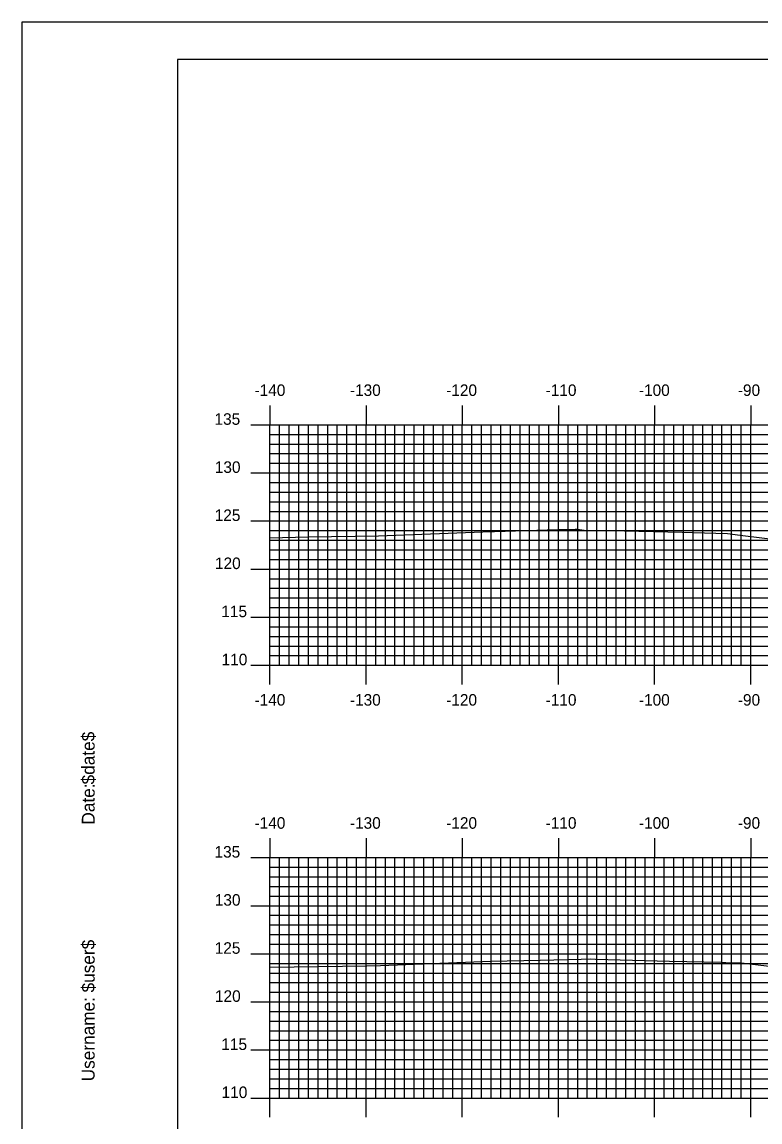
# Model space of a CAD drawing. Extents: x 842962 to 843305, y 363538 to 363758.
# Drawn here: x 842962.1 to 843038.9, y 363643.2 to 363757.6 of the extents above; entities that cross this region are included whole.
import ezdxf

# ---------------------------------------------------------------- set-up
doc = ezdxf.new("R2010")
doc.units = 0
for name, color, linetype in [('BORDER', 7, 'Continuous'), ('H_V ANNOTATION', 7, 'Continuous'), ('M_Roadway_Centerline', 7, 'Continuous'), ('MAJOR', 7, 'Continuous'), ('MINOR', 7, 'Continuous'), ('PLOT BOUNDARY', 7, 'Continuous'), ('S_Roadway_Centerline', 7, 'Continuous')]:
    doc.layers.add(name, color=color, linetype=linetype)

msp = doc.modelspace()

# ---------------------------------------------------------------- linework, layer by layer
at = {"layer": 'BORDER'}
msp.add_lwpolyline([(842978.31, 363543.72), (843298.31, 363543.72), (843298.31, 363753.72), (842978.31, 363753.72)], close=True, dxfattribs=at)
at = {"layer": 'MAJOR'}
for p, q in [((842987.91, 363717.73), (842987.91, 363715.72)), ((842997.91, 363717.73), (842997.91, 363715.72)), ((843007.91, 363717.73), (843007.91, 363715.72)), ((843017.91, 363717.73), (843017.91, 363715.72)), ((843027.91, 363717.73), (843027.91, 363715.72)), ((843037.91, 363717.73), (843037.91, 363715.72)), ((842985.91, 363715.72), (842987.91, 363715.72)), ((842987.91, 363715.72), (843267.91, 363715.72)), ((842987.91, 363690.72), (842987.91, 363715.72)), ((842987.91, 363690.72), (842987.91, 363715.72)), ((842987.91, 363715.72), (843267.91, 363715.72)), ((842997.91, 363690.72), (842997.91, 363715.72)), ((843007.91, 363690.72), (843007.91, 363715.72)), ((843017.91, 363690.72), (843017.91, 363715.72)), ((843027.91, 363690.72), (843027.91, 363715.72)), ((843037.91, 363690.72), (843037.91, 363715.72)), ((842985.91, 363710.72), (842987.91, 363710.72)), ((842987.91, 363710.72), (843267.91, 363710.72)), ((842985.91, 363705.72), (842987.91, 363705.72)), ((842987.91, 363705.72), (843267.91, 363705.72)), ((842985.91, 363700.72), (842987.91, 363700.72)), ((842987.91, 363700.72), (843267.91, 363700.72)), ((842985.91, 363695.72), (842987.91, 363695.72)), ((842987.91, 363695.72), (843267.91, 363695.72)), ((842985.91, 363690.72), (842987.91, 363690.72)), ((842987.91, 363690.72), (843267.91, 363690.72)), ((842987.91, 363690.72), (843267.91, 363690.72)), ((842987.91, 363688.72), (842987.91, 363690.72)), ((842997.91, 363688.72), (842997.91, 363690.72)), ((843007.91, 363688.72), (843007.91, 363690.72)), ((843017.91, 363688.72), (843017.91, 363690.72)), ((843027.91, 363688.72), (843027.91, 363690.72)), ((843037.91, 363688.72), (843037.91, 363690.72)), ((842987.91, 363672.73), (842987.91, 363670.72)), ((842997.91, 363672.73), (842997.91, 363670.72)), ((843007.91, 363672.73), (843007.91, 363670.72)), ((843017.91, 363672.73), (843017.91, 363670.72)), ((843027.91, 363672.73), (843027.91, 363670.72)), ((843037.91, 363672.73), (843037.91, 363670.72)), ((842985.91, 363670.72), (842987.91, 363670.72)), ((842987.91, 363670.72), (843267.91, 363670.72)), ((842987.91, 363645.72), (842987.91, 363670.72)), ((842987.91, 363645.72), (842987.91, 363670.72)), ((842987.91, 363670.72), (843267.91, 363670.72)), ((842997.91, 363645.72), (842997.91, 363670.72)), ((843007.91, 363645.72), (843007.91, 363670.72)), ((843017.91, 363645.72), (843017.91, 363670.72)), ((843027.91, 363645.72), (843027.91, 363670.72)), ((843037.91, 363645.72), (843037.91, 363670.72)), ((842985.91, 363665.72), (842987.91, 363665.72)), ((842987.91, 363665.72), (843267.91, 363665.72)), ((842985.91, 363660.72), (842987.91, 363660.72)), ((842987.91, 363660.72), (843267.91, 363660.72)), ((842985.91, 363655.72), (842987.91, 363655.72)), ((842987.91, 363655.72), (843267.91, 363655.72)), ((842985.91, 363650.72), (842987.91, 363650.72)), ((842987.91, 363650.72), (843267.91, 363650.72)), ((842985.91, 363645.72), (842987.91, 363645.72)), ((842987.91, 363645.72), (843267.91, 363645.72)), ((842987.91, 363645.72), (843267.91, 363645.72)), ((842987.91, 363643.72), (842987.91, 363645.72)), ((842997.91, 363643.72), (842997.91, 363645.72)), ((843007.91, 363643.72), (843007.91, 363645.72)), ((843017.91, 363643.72), (843017.91, 363645.72)), ((843027.91, 363643.72), (843027.91, 363645.72)), ((843037.91, 363643.72), (843037.91, 363645.72))]:
    msp.add_line(p, q, dxfattribs=at)
at = {"layer": 'MINOR'}
for p, q in [((842988.91, 363690.72), (842988.91, 363715.72)), ((842989.91, 363690.72), (842989.91, 363715.72)), ((842990.91, 363690.72), (842990.91, 363715.72)), ((842991.91, 363690.72), (842991.91, 363715.72)), ((842992.91, 363690.72), (842992.91, 363715.72)), ((842993.91, 363690.72), (842993.91, 363715.72)), ((842994.91, 363690.72), (842994.91, 363715.72)), ((842995.91, 363690.72), (842995.91, 363715.72)), ((842996.91, 363690.72), (842996.91, 363715.72)), ((842998.91, 363690.72), (842998.91, 363715.72)), ((842999.91, 363690.72), (842999.91, 363715.72)), ((843000.91, 363690.72), (843000.91, 363715.72)), ((843001.91, 363690.72), (843001.91, 363715.72)), ((843002.91, 363690.72), (843002.91, 363715.72)), ((843003.91, 363690.72), (843003.91, 363715.72)), ((843004.91, 363690.72), (843004.91, 363715.72)), ((843005.91, 363690.72), (843005.91, 363715.72)), ((843006.91, 363690.72), (843006.91, 363715.72)), ((843008.91, 363690.72), (843008.91, 363715.72)), ((843009.91, 363690.72), (843009.91, 363715.72)), ((843010.91, 363690.72), (843010.91, 363715.72)), ((843011.91, 363690.72), (843011.91, 363715.72)), ((843012.91, 363690.72), (843012.91, 363715.72)), ((843013.91, 363690.72), (843013.91, 363715.72)), ((843014.91, 363690.72), (843014.91, 363715.72)), ((843015.91, 363690.72), (843015.91, 363715.72)), ((843016.91, 363690.72), (843016.91, 363715.72)), ((843018.91, 363690.72), (843018.91, 363715.72)), ((843019.91, 363690.72), (843019.91, 363715.72)), ((843020.91, 363690.72), (843020.91, 363715.72)), ((843021.91, 363690.72), (843021.91, 363715.72)), ((843022.91, 363690.72), (843022.91, 363715.72)), ((843023.91, 363690.72), (843023.91, 363715.72)), ((843024.91, 363690.72), (843024.91, 363715.72)), ((843025.91, 363690.72), (843025.91, 363715.72)), ((843026.91, 363690.72), (843026.91, 363715.72)), ((843028.91, 363690.72), (843028.91, 363715.72)), ((843029.91, 363690.72), (843029.91, 363715.72)), ((843030.91, 363690.72), (843030.91, 363715.72)), ((843031.91, 363690.72), (843031.91, 363715.72)), ((843032.91, 363690.72), (843032.91, 363715.72)), ((843033.91, 363690.72), (843033.91, 363715.72)), ((843034.91, 363690.72), (843034.91, 363715.72)), ((843035.91, 363690.72), (843035.91, 363715.72)), ((843036.91, 363690.72), (843036.91, 363715.72)), ((842987.91, 363714.72), (843267.91, 363714.72)), ((842987.91, 363714.72), (842989.92, 363714.72)), ((842987.91, 363713.72), (843267.91, 363713.72)), ((842987.91, 363713.72), (842989.92, 363713.72)), ((842987.91, 363712.72), (843267.91, 363712.72)), ((842987.91, 363712.72), (842989.92, 363712.72)), ((842987.91, 363711.72), (843267.91, 363711.72)), ((842987.91, 363711.72), (842989.92, 363711.72)), ((842987.91, 363709.72), (843267.91, 363709.72)), ((842987.91, 363709.72), (842989.92, 363709.72)), ((842987.91, 363708.72), (843267.91, 363708.72)), ((842987.91, 363708.72), (842989.92, 363708.72)), ((842987.91, 363707.72), (843267.91, 363707.72)), ((842987.91, 363707.72), (842989.92, 363707.72)), ((842987.91, 363706.72), (843267.91, 363706.72)), ((842987.91, 363706.72), (842989.92, 363706.72)), ((842987.91, 363704.72), (843267.91, 363704.72)), ((842987.91, 363704.72), (842989.92, 363704.72)), ((842987.91, 363703.72), (843267.91, 363703.72)), ((842987.91, 363703.72), (842989.92, 363703.72)), ((842987.91, 363702.72), (843267.91, 363702.72)), ((842987.91, 363702.72), (842989.92, 363702.72)), ((842987.91, 363701.72), (843267.91, 363701.72)), ((842987.91, 363701.72), (842989.92, 363701.72)), ((842987.91, 363699.72), (843267.91, 363699.72)), ((842987.91, 363699.72), (842989.92, 363699.72)), ((842987.91, 363698.72), (843267.91, 363698.72)), ((842987.91, 363698.72), (842989.92, 363698.72)), ((842987.91, 363697.72), (843267.91, 363697.72)), ((842987.91, 363697.72), (842989.92, 363697.72)), ((842987.91, 363696.72), (843267.91, 363696.72)), ((842987.91, 363696.72), (842989.92, 363696.72)), ((842987.91, 363694.72), (843267.91, 363694.72)), ((842987.91, 363694.72), (842989.92, 363694.72)), ((842987.91, 363693.72), (843267.91, 363693.72)), ((842987.91, 363693.72), (842989.92, 363693.72)), ((842987.91, 363692.72), (843267.91, 363692.72)), ((842987.91, 363692.72), (842989.92, 363692.72)), ((842987.91, 363691.72), (843267.91, 363691.72)), ((842987.91, 363691.72), (842989.92, 363691.72)), ((842988.91, 363645.72), (842988.91, 363670.72)), ((842989.91, 363645.72), (842989.91, 363670.72)), ((842990.91, 363645.72), (842990.91, 363670.72)), ((842991.91, 363645.72), (842991.91, 363670.72)), ((842992.91, 363645.72), (842992.91, 363670.72)), ((842993.91, 363645.72), (842993.91, 363670.72)), ((842994.91, 363645.72), (842994.91, 363670.72)), ((842995.91, 363645.72), (842995.91, 363670.72)), ((842996.91, 363645.72), (842996.91, 363670.72)), ((842998.91, 363645.72), (842998.91, 363670.72)), ((842999.91, 363645.72), (842999.91, 363670.72)), ((843000.91, 363645.72), (843000.91, 363670.72)), ((843001.91, 363645.72), (843001.91, 363670.72)), ((843002.91, 363645.72), (843002.91, 363670.72)), ((843003.91, 363645.72), (843003.91, 363670.72)), ((843004.91, 363645.72), (843004.91, 363670.72)), ((843005.91, 363645.72), (843005.91, 363670.72)), ((843006.91, 363645.72), (843006.91, 363670.72)), ((843008.91, 363645.72), (843008.91, 363670.72)), ((843009.91, 363645.72), (843009.91, 363670.72)), ((843010.91, 363645.72), (843010.91, 363670.72)), ((843011.91, 363645.72), (843011.91, 363670.72)), ((843012.91, 363645.72), (843012.91, 363670.72)), ((843013.91, 363645.72), (843013.91, 363670.72)), ((843014.91, 363645.72), (843014.91, 363670.72)), ((843015.91, 363645.72), (843015.91, 363670.72)), ((843016.91, 363645.72), (843016.91, 363670.72)), ((843018.91, 363645.72), (843018.91, 363670.72)), ((843019.91, 363645.72), (843019.91, 363670.72)), ((843020.91, 363645.72), (843020.91, 363670.72)), ((843021.91, 363645.72), (843021.91, 363670.72)), ((843022.91, 363645.72), (843022.91, 363670.72)), ((843023.91, 363645.72), (843023.91, 363670.72)), ((843024.91, 363645.72), (843024.91, 363670.72)), ((843025.91, 363645.72), (843025.91, 363670.72)), ((843026.91, 363645.72), (843026.91, 363670.72)), ((843028.91, 363645.72), (843028.91, 363670.72)), ((843029.91, 363645.72), (843029.91, 363670.72)), ((843030.91, 363645.72), (843030.91, 363670.72)), ((843031.91, 363645.72), (843031.91, 363670.72)), ((843032.91, 363645.72), (843032.91, 363670.72)), ((843033.91, 363645.72), (843033.91, 363670.72)), ((843034.91, 363645.72), (843034.91, 363670.72)), ((843035.91, 363645.72), (843035.91, 363670.72)), ((843036.91, 363645.72), (843036.91, 363670.72)), ((842987.91, 363669.72), (843267.91, 363669.72)), ((842987.91, 363669.72), (842989.92, 363669.72)), ((842987.91, 363668.72), (843267.91, 363668.72)), ((842987.91, 363668.72), (842989.92, 363668.72)), ((842987.91, 363667.72), (843267.91, 363667.72)), ((842987.91, 363667.72), (842989.92, 363667.72)), ((842987.91, 363666.72), (843267.91, 363666.72)), ((842987.91, 363666.72), (842989.92, 363666.72)), ((842987.91, 363664.72), (843267.91, 363664.72)), ((842987.91, 363664.72), (842989.92, 363664.72)), ((842987.91, 363663.72), (843267.91, 363663.72)), ((842987.91, 363663.72), (842989.92, 363663.72)), ((842987.91, 363662.72), (843267.91, 363662.72)), ((842987.91, 363662.72), (842989.92, 363662.72)), ((842987.91, 363661.72), (843267.91, 363661.72)), ((842987.91, 363661.72), (842989.92, 363661.72)), ((842987.91, 363659.72), (843267.91, 363659.72)), ((842987.91, 363659.72), (842989.92, 363659.72)), ((842987.91, 363658.72), (843267.91, 363658.72)), ((842987.91, 363658.72), (842989.92, 363658.72)), ((842987.91, 363657.72), (843267.91, 363657.72)), ((842987.91, 363657.72), (842989.92, 363657.72)), ((842987.91, 363656.72), (843267.91, 363656.72)), ((842987.91, 363656.72), (842989.92, 363656.72)), ((842987.91, 363654.72), (843267.91, 363654.72)), ((842987.91, 363654.72), (842989.92, 363654.72)), ((842987.91, 363653.72), (843267.91, 363653.72)), ((842987.91, 363653.72), (842989.92, 363653.72)), ((842987.91, 363652.72), (843267.91, 363652.72)), ((842987.91, 363652.72), (842989.92, 363652.72)), ((842987.91, 363651.72), (843267.91, 363651.72)), ((842987.91, 363651.72), (842989.92, 363651.72)), ((842987.91, 363649.72), (843267.91, 363649.72)), ((842987.91, 363649.72), (842989.92, 363649.72)), ((842987.91, 363648.72), (843267.91, 363648.72)), ((842987.91, 363648.72), (842989.92, 363648.72)), ((842987.91, 363647.72), (843267.91, 363647.72)), ((842987.91, 363647.72), (842989.92, 363647.72)), ((842987.91, 363646.72), (843267.91, 363646.72)), ((842987.91, 363646.72), (842989.92, 363646.72))]:
    msp.add_line(p, q, dxfattribs=at)
at = {"layer": 'PLOT BOUNDARY'}
msp.add_lwpolyline([(842962.12, 363537.6), (843302.12, 363537.6), (843302.12, 363757.6), (842962.12, 363757.6)], close=True, dxfattribs=at)
at = {"layer": 'S_Roadway_Centerline'}
for points in [[(842987.91, 363703.98), (842991.89, 363704.06), (842999.18, 363704.16), (843010.95, 363704.63), (843011.15, 363704.64), (843011.25, 363704.64), (843017.84, 363704.82), (843019.63, 363704.87), (843019.86, 363704.87), (843020.58, 363704.78), (843023.29, 363704.73), (843030.76, 363704.57), (843034.28, 363704.47), (843035.47, 363704.43), (843036.8, 363704.25), (843045.25, 363703.21)], [(842987.91, 363659.34), (842997.98, 363659.48), (842999.41, 363659.51), (843010.86, 363659.95), (843016, 363660.06), (843020.27, 363660.16), (843021.26, 363660.19), (843021.77, 363660.17), (843029.46, 363659.96), (843034.82, 363659.83), (843035.81, 363659.79), (843036.93, 363659.78), (843041.29, 363659.27)]]:
    msp.add_lwpolyline(points, dxfattribs=at)

# ---------------------------------------------------------------- texts
at = {"layer": 'BORDER'}
for s, p in [('$date$', (842969.68, 363678.33)), ('Date:', (842969.68, 363674.15)), ('$user$', (842969.68, 363656.7)), ('Username:', (842969.68, 363647.46))]:
    msp.add_text(s, height=1.339, rotation=90, dxfattribs=at).set_placement(p)
at = {"layer": 'H_V ANNOTATION'}
for s, p in [('-140', (842986.3, 363718.72)), ('-130', (842996.22, 363718.72)), ('-120', (843006.23, 363718.72)), ('-110', (843016.57, 363718.72)), ('-100', (843026.27, 363718.72)), ('-90', (843036.56, 363718.72)), ('135', (842982.14, 363715.72)), ('130', (842982.17, 363710.72)), ('125', (842982.16, 363705.72)), ('120', (842982.19, 363700.72)), ('115', (842982.85, 363695.72)), ('110', (842982.88, 363690.72)), ('-140', (842986.3, 363686.52)), ('-130', (842996.22, 363686.52)), ('-120', (843006.23, 363686.52)), ('-110', (843016.57, 363686.52)), ('-100', (843026.27, 363686.52)), ('-90', (843036.56, 363686.52)), ('-140', (842986.3, 363673.72)), ('-130', (842996.22, 363673.72)), ('-120', (843006.23, 363673.72)), ('-110', (843016.57, 363673.72)), ('-100', (843026.27, 363673.72)), ('-90', (843036.56, 363673.72)), ('135', (842982.14, 363670.72)), ('130', (842982.17, 363665.72)), ('125', (842982.16, 363660.72)), ('120', (842982.19, 363655.72)), ('115', (842982.85, 363650.72)), ('110', (842982.88, 363645.72))]:
    msp.add_text(s, height=1.2, dxfattribs=at).set_placement(p)
at = {"layer": 'M_Roadway_Centerline'}
for s, p in [('C', (843019.63, 363704.87)), ('L', (843019.63, 363704.87)), ('C', (843021.25, 363660.19)), ('L', (843021.26, 363660.18))]:
    msp.add_text(s, height=0.0146, dxfattribs=at).set_placement(p)
at = {"layer": 'MAJOR'}
for p in [(842987.9, 363690.72), (842987.9, 363645.72)]:
    msp.add_text('-', height=0.012, dxfattribs=at).set_placement(p)

doc.saveas('drawing.dxf')
